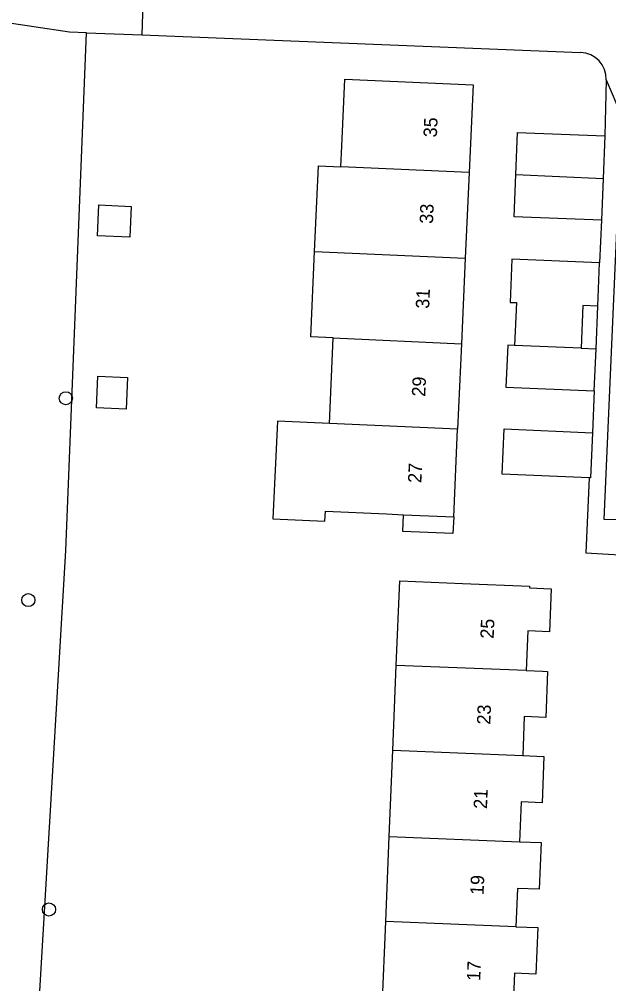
# Model space of a CAD drawing. Extents: x 160732 to 162105, y 387428 to 388479.
# Drawn here: x 161061 to 161104.9, y 387617.3 to 387689.2 of the extents above; entities that cross this region are included whole.
import ezdxf

# ---------------------------------------------------------------- set-up
doc = ezdxf.new("R2010")
doc.units = 0
for name, color, linetype in [('IMGEO_Boom', 7, 'Continuous'), ('IMGEO_Loofbos', 7, 'Continuous'), ('IMGEO_Pand', 7, 'Continuous'), ('IMGEO_Pand_nummerreeks', 7, 'Continuous'), ('IMGEO_Voetpad_gesloten', 7, 'Continuous'), ('IMGEO_Voetpad_open', 7, 'Continuous')]:
    doc.layers.add(name, color=color, linetype=linetype)

msp = doc.modelspace()

# ---------------------------------------------------------------- linework, layer by layer
at = {"layer": 'IMGEO_Boom'}
for centre in [(161064.489, 387660.932), (161061.691, 387645.887), (161063.23, 387622.821)]:
    msp.add_circle(centre, 0.489, dxfattribs=at)
at = {"layer": 'IMGEO_Loofbos'}
msp.add_lwpolyline([(161061.574, 387600.31), (161064.492, 387649.589), (161066.023, 387688.174)], dxfattribs=at)
at = {"layer": 'IMGEO_Pand'}
for points in [[(161084.97, 387678.185), (161085.039, 387679.726), (161085.262, 387684.721), (161094.815, 387684.294), (161094.522, 387677.756)], [(161098.002, 387677.6), (161098.125, 387680.744), (161104.624, 387680.488)], [(161104.624, 387680.488), (161104.499, 387677.308)], [(161083.009, 387671.88), (161083.296, 387678.26), (161084.97, 387678.185)], [(161094.522, 387677.756), (161084.97, 387678.185)], [(161094.522, 387677.756), (161094.237, 387671.378)], [(161104.377, 387674.199), (161097.878, 387674.455), (161098.002, 387677.6)], [(161098.002, 387677.6), (161104.499, 387677.308)], [(161104.499, 387677.308), (161104.377, 387674.199)], [(161069.258, 387672.929), (161066.837, 387673.037), (161066.94, 387675.338), (161069.361, 387675.23), (161069.258, 387672.929)], [(161084.399, 387665.424), (161082.722, 387665.499), (161083.009, 387671.88)], [(161083.009, 387671.88), (161094.237, 387671.378)], [(161094.237, 387671.378), (161093.951, 387664.997)], [(161104.242, 387671.026), (161097.717, 387671.302), (161097.58, 387668.077), (161098.044, 387668.057), (161097.915, 387664.863)], [(161104.105, 387667.801), (161104.242, 387671.026)], [(161104.105, 387667.801), (161102.997, 387667.848), (161102.867, 387664.662)], [(161084.113, 387659.043), (161084.399, 387665.424)], [(161084.399, 387665.424), (161093.951, 387664.997)], [(161093.951, 387664.997), (161093.665, 387658.615)], [(161097.915, 387664.863), (161097.397, 387664.884), (161097.271, 387661.76), (161103.85, 387661.493)], [(161102.867, 387664.662), (161097.915, 387664.863)], [(161102.867, 387664.662), (161103.976, 387664.617)], [(161103.85, 387661.493), (161103.976, 387664.617)], [(161068.969, 387660.117), (161066.774, 387660.215), (161066.879, 387662.573), (161069.074, 387662.475), (161068.969, 387660.117)], [(161084.113, 387659.043), (161080.239, 387659.217), (161079.912, 387651.931), (161083.787, 387651.757), (161083.821, 387652.512), (161088.378, 387652.308), (161089.633, 387652.252)], [(161093.665, 387658.615), (161084.113, 387659.043)], [(161093.373, 387652.085), (161093.665, 387658.615)], [(161103.478, 387654.999), (161096.992, 387655.271), (161097.133, 387658.641), (161103.703, 387658.365)], [(161103.703, 387658.365), (161103.562, 387654.995), (161103.478, 387654.999)], [(161093.373, 387652.085), (161093.317, 387650.837), (161089.577, 387651.004), (161089.633, 387652.252)], [(161089.633, 387652.252), (161093.373, 387652.085)], [(161089.097, 387641.013), (161089.353, 387647.31), (161094.034, 387647.119), (161099.029, 387646.916), (161099.023, 387646.79), (161100.643, 387646.724), (161100.513, 387643.521), (161098.892, 387643.587), (161098.772, 387640.631)], [(161088.84, 387634.689), (161089.097, 387641.013)], [(161098.772, 387640.631), (161089.097, 387641.013)], [(161098.772, 387640.631), (161099.996, 387640.581), (161100.367, 387640.566), (161100.227, 387637.143), (161098.636, 387637.207), (161098.517, 387634.306)], [(161088.578, 387628.259), (161088.84, 387634.689)], [(161088.84, 387634.689), (161098.517, 387634.306)], [(161098.517, 387634.306), (161100.097, 387634.239), (161099.957, 387630.776), (161098.397, 387630.84), (161098.276, 387627.875)], [(161088.32, 387621.923), (161088.578, 387628.259)], [(161088.578, 387628.259), (161098.276, 387627.875)], [(161098.276, 387627.875), (161099.882, 387627.81), (161099.74, 387624.327), (161098.123, 387624.393), (161098.006, 387621.54)], [(161088.059, 387615.506), (161088.32, 387621.923)], [(161098.006, 387621.54), (161088.32, 387621.923)], [(161098.006, 387621.54), (161099.641, 387621.472), (161099.5, 387618.01), (161097.898, 387618.075), (161097.778, 387615.121)]]:
    msp.add_lwpolyline(points, dxfattribs=at)
at = {"layer": 'IMGEO_Voetpad_gesloten'}
for points in [[(161070.237, 387691.194), (161070.141, 387688.01)], [(161066.023, 387688.174), (161064.758, 387688.224), (161059.419, 387689.025)], [(161066.023, 387688.174), (161070.141, 387688.01)]]:
    msp.add_lwpolyline(points, dxfattribs=at)
at = {"layer": 'IMGEO_Voetpad_open'}
for points in [[(161070.141, 387688.01), (161102.832, 387686.71)], [(161104.74, 387684.657), (161104.624, 387680.488)], [(161104.74, 387684.657), (161105.904, 387681.934)], [(161105.716, 387652.188), (161105.484, 387651.856), (161104.578, 387651.887), (161105.904, 387681.934)], [(161104.377, 387674.199), (161104.242, 387671.026)], [(161103.976, 387664.617), (161104.105, 387667.801)], [(161103.85, 387661.493), (161103.703, 387658.365)], [(161103.478, 387654.999), (161103.227, 387649.406), (161105.739, 387649.265)]]:
    msp.add_lwpolyline(points, dxfattribs=at)
msp.add_arc((161102.742, 387684.713), 1.999, 358.39113, 87.4159, dxfattribs=at)

# ---------------------------------------------------------------- texts
at = {"layer": 'IMGEO_Pand_nummerreeks'}
for s, rotation, p in [('35', 87.43658, (161092.117, 387680.361)), ('33', 87.43658, (161091.828, 387673.919)), ('31', 87.43658, (161091.545, 387667.59)), ('29', 87.43658, (161091.252, 387661.035)), ('27', 87.43909, (161090.963, 387654.594)), ('25', 87.75089, (161096.352, 387642.991)), ('23', 87.75089, (161096.1, 387636.592)), ('21', 87.75089, (161095.853, 387630.306)), ('19', 87.75089, (161095.601, 387623.885)), ('17', 87.75089, (161095.35, 387617.487))]:
    msp.add_text(s, height=1, rotation=rotation, dxfattribs=at).set_placement(p)

doc.saveas('drawing.dxf')
